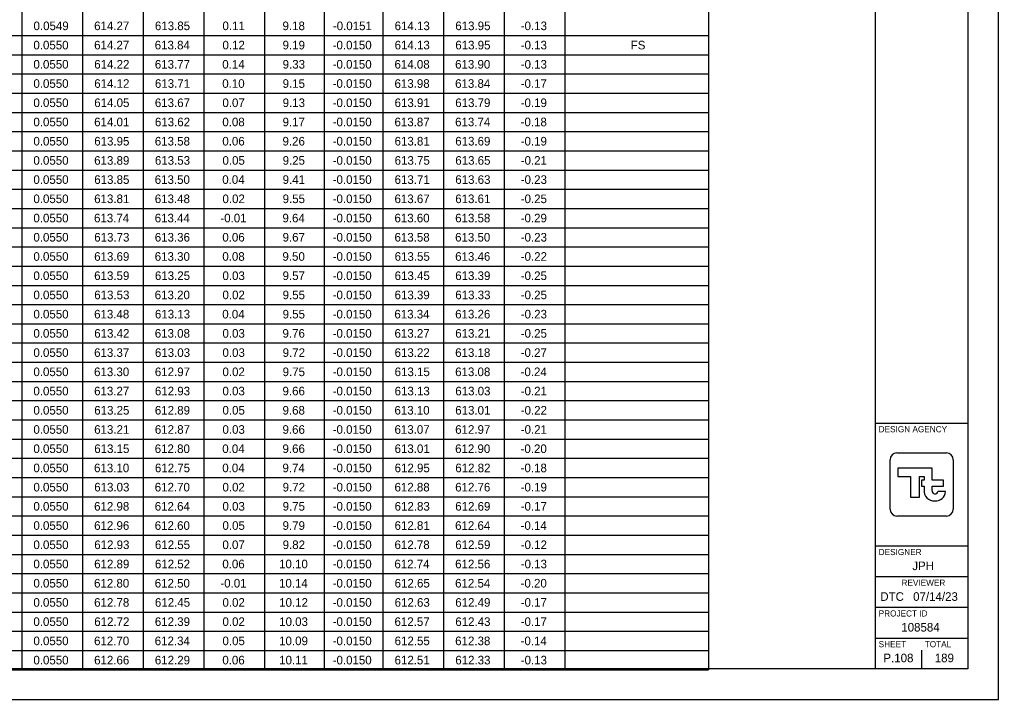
# Model space of a CAD drawing. Extents: x 0 to 34, y 0 to 22.
# Drawn here: x 18.06 to 34, y 0 to 11.07 of the extents above; entities that cross this region are included whole.
import ezdxf

# ---------------------------------------------------------------- set-up
doc = ezdxf.new("R2010")
doc.units = 0
for name, color, linetype in [('SH_Border', 7, 'Continuous'), ('SH_Cut_Line', 7, 'Continuous'), ('SH_Data', 7, 'Continuous'), ('SH_Text', 7, 'Continuous')]:
    doc.layers.add(name, color=color, linetype=linetype)

msp = doc.modelspace()

# ---------------------------------------------------------------- linework, layer by layer
at = {"layer": 'SH_Border'}
for p, q in [((32, 0.5), (32, 21.5)), ((32, 4.5), (33.5, 4.5)), ((32, 2.5), (33.5, 2.5)), ((32, 2), (33.5, 2)), ((32, 1.5), (33.5, 1.5)), ((32, 1), (33.5, 1))]:
    msp.add_line(p, q, dxfattribs=at)
msp.add_lwpolyline([(1.5, 21.5), (33.5, 21.5), (33.5, 0.5), (1.5, 0.5)], close=True, dxfattribs=at)
at = {"layer": 'SH_Cut_Line'}
msp.add_lwpolyline([(0, 0), (34, 0), (34, 22), (0, 22)], close=True, dxfattribs=at)
at = {"layer": 'SH_Data'}
for p, q in [((32.75, 3.5), (32.75, 3.5)), ((32.791, 3.415), (32.791, 3.415)), ((33.136, 3.385), (33.015, 3.385)), ((32.75, 0.5), (32.75, 0.8)), ((32.375, 0.675), (32.375, 0.675))]:
    msp.add_line(p, q, dxfattribs=at)
for points in [[(32.348, 4.014), (33.152, 4.014)], [(32.236, 3.099), (32.236, 3.901)], [(33.264, 3.901), (33.264, 3.099)], [(32.922, 3.399), (32.922, 3.47), (33.107, 3.47), (33.107, 3.568), (32.922, 3.568), (32.922, 3.768), (32.361, 3.768), (32.361, 3.632), (32.566, 3.632), (32.566, 3.294), (32.715, 3.294), (32.715, 3.63), (32.79, 3.63), (32.79, 3.568), (32.748, 3.568), (32.748, 3.47), (32.79, 3.47), (32.79, 3.415), (32.791, 3.415)], [(33.152, 2.986), (32.348, 2.986)]]:
    msp.add_lwpolyline(points, dxfattribs=at)
for centre, radius, start, end in [((32.348, 3.901), 0.113, 90, 180), ((33.152, 3.901), 0.113, 360, 90), ((32.949, 3.392), 0.16, 171.8856, 274.8323), ((32.968, 3.392), 0.0473, 171.8856, 350.9243), ((32.976, 3.392), 0.16, 265.1677, 357.3201), ((32.348, 3.099), 0.113, 180, 270), ((33.152, 3.099), 0.113, 270, 360)]:
    msp.add_arc(centre, radius, start, end, dxfattribs=at)
at = {"layer": 'SH_Text'}
for p, q in [((29.277, 21.5), (29.277, 0.484)), ((26.938, 20.396), (26.938, 0.484)), ((22.046, 19.853), (22.046, 0.484)), ((18.093, 19.54), (18.093, 0.484)), ((19.081, 19.54), (19.081, 0.484)), ((20.07, 19.54), (20.07, 0.484)), ((21.058, 19.54), (21.058, 0.484)), ((23.018, 19.54), (23.018, 0.484)), ((23.973, 19.54), (23.973, 0.484)), ((24.961, 19.54), (24.961, 0.484)), ((25.95, 19.54), (25.95, 0.484)), ((4.225, 10.811), (29.277, 10.811)), ((4.225, 10.498), (29.277, 10.498)), ((4.225, 10.185), (29.277, 10.185)), ((4.225, 9.872), (29.277, 9.872)), ((4.225, 9.559), (29.277, 9.559)), ((4.225, 9.246), (29.277, 9.246)), ((4.225, 8.933), (29.277, 8.933)), ((4.225, 8.62), (29.277, 8.62)), ((4.225, 8.307), (29.277, 8.307)), ((4.225, 7.994), (29.277, 7.994)), ((4.225, 7.681), (29.277, 7.681)), ((4.225, 7.368), (29.277, 7.368)), ((4.225, 7.055), (29.277, 7.055)), ((4.225, 6.742), (29.277, 6.742)), ((4.225, 6.429), (29.277, 6.429)), ((4.225, 6.116), (29.277, 6.116)), ((4.225, 5.804), (29.277, 5.804)), ((4.225, 5.491), (29.277, 5.491)), ((4.225, 5.178), (29.277, 5.178)), ((4.225, 4.865), (29.277, 4.865)), ((4.225, 4.552), (29.277, 4.552)), ((4.225, 4.239), (29.277, 4.239)), ((4.225, 3.926), (29.277, 3.926)), ((4.225, 3.613), (29.277, 3.613)), ((4.225, 3.3), (29.277, 3.3)), ((4.225, 2.987), (29.277, 2.987)), ((4.225, 2.674), (29.277, 2.674)), ((4.225, 2.361), (29.277, 2.361)), ((4.225, 2.048), (29.277, 2.048)), ((4.225, 1.735), (29.277, 1.735)), ((4.225, 1.422), (29.277, 1.422)), ((4.225, 1.109), (29.277, 1.109)), ((4.225, 0.796), (29.277, 0.796)), ((4.225, 0.484), (29.277, 0.484))]:
    msp.add_line(p, q, dxfattribs=at)

# ---------------------------------------------------------------- texts
at = {"layer": 'SH_Data'}
for s, height, p in [('DESIGN AGENCY', 0.1, (32.05, 4.35)), ('DESIGNER', 0.1, (32.05, 2.35)), ('JPH', 0.14, (32.598, 2.105)), ('REVIEWER', 0.1, (32.422, 1.85)), ('DTC', 0.14, (32.076, 1.605)), ('07/14/23', 0.14, (32.611, 1.605)), ('PROJECT ID', 0.1, (32.05, 1.35)), ('108584', 0.14, (32.418, 1.105)), ('SHEET', 0.1, (32.05, 0.85)), ('TOTAL', 0.1, (32.8, 0.85)), ('P.108', 0.14, (32.127, 0.605)), ('189', 0.14, (32.963, 0.605))]:
    msp.add_text(s, height=height, dxfattribs=at).set_placement(p)
at = {"layer": 'SH_Text'}
for s, p in [('0.0549', (18.286, 10.897)), ('614.27', (19.273, 10.897)), ('613.85', (20.263, 10.897)), ('0.11', (21.363, 10.897)), ('9.18', (22.341, 10.897)), ('-0.0151', (23.161, 10.897)), ('614.13', (24.167, 10.897)), ('613.95', (25.155, 10.897)), ('-0.13', (26.221, 10.897)), ('0.0550', (18.284, 10.584)), ('614.27', (19.273, 10.584)), ('613.84', (20.26, 10.584)), ('0.12', (21.363, 10.584)), ('9.19', (22.342, 10.584)), ('-0.0150', (23.158, 10.584)), ('614.13', (24.167, 10.584)), ('613.95', (25.155, 10.584)), ('-0.13', (26.221, 10.584)), ('FS', (28.012, 10.584)), ('0.0550', (18.284, 10.271)), ('614.22', (19.275, 10.271)), ('613.77', (20.262, 10.271)), ('0.14', (21.36, 10.271)), ('9.33', (22.343, 10.271)), ('-0.0150', (23.158, 10.271)), ('614.08', (24.165, 10.271)), ('613.90', (25.152, 10.271)), ('-0.13', (26.221, 10.271)), ('0.0550', (18.284, 9.958)), ('614.12', (19.275, 9.958)), ('613.71', (20.263, 9.958)), ('0.10', (21.36, 9.958)), ('9.15', (22.343, 9.958)), ('-0.0150', (23.158, 9.958)), ('613.98', (24.165, 9.958)), ('613.84', (25.152, 9.958)), ('-0.17', (26.22, 9.958)), ('0.0550', (18.284, 9.645)), ('614.05', (19.275, 9.645)), ('613.67', (20.262, 9.645)), ('0.07', (21.362, 9.645)), ('9.13', (22.343, 9.645)), ('-0.0150', (23.158, 9.645)), ('613.91', (24.166, 9.645)), ('613.79', (25.154, 9.645)), ('-0.19', (26.22, 9.645)), ('0.0550', (18.284, 9.332)), ('614.01', (19.274, 9.332)), ('613.62', (20.263, 9.332)), ('0.08', (21.361, 9.332)), ('9.17', (22.342, 9.332)), ('-0.0150', (23.158, 9.332)), ('613.87', (24.165, 9.332)), ('613.74', (25.152, 9.332)), ('-0.18', (26.219, 9.332)), ('0.0550', (18.284, 9.019)), ('613.95', (19.275, 9.019)), ('613.58', (20.261, 9.019)), ('0.06', (21.361, 9.019)), ('9.26', (22.341, 9.019)), ('-0.0150', (23.158, 9.019)), ('613.81', (24.166, 9.019)), ('613.69', (25.154, 9.019)), ('-0.19', (26.22, 9.019)), ('0.0550', (18.284, 8.706)), ('613.89', (19.274, 8.706)), ('613.53', (20.263, 8.706)), ('0.05', (21.363, 8.706)), ('9.25', (22.343, 8.706)), ('-0.0150', (23.158, 8.706)), ('613.75', (24.167, 8.706)), ('613.65', (25.155, 8.706)), ('-0.21', (26.221, 8.706)), ('0.0550', (18.284, 8.394)), ('613.85', (19.275, 8.394)), ('613.50', (20.26, 8.394)), ('0.04', (21.36, 8.394)), ('9.41', (22.343, 8.394)), ('-0.0150', (23.158, 8.394)), ('613.71', (24.166, 8.394)), ('613.63', (25.155, 8.394)), ('-0.23', (26.221, 8.394)), ('0.0550', (18.284, 8.081)), ('613.81', (19.274, 8.081)), ('613.48', (20.261, 8.081)), ('0.02', (21.363, 8.081)), ('9.55', (22.343, 8.081)), ('-0.0150', (23.158, 8.081)), ('613.67', (24.165, 8.081)), ('613.61', (25.154, 8.081)), ('-0.25', (26.221, 8.081)), ('0.0550', (18.284, 7.768)), ('613.74', (19.272, 7.768)), ('613.44', (20.26, 7.768)), ('-0.01', (21.329, 7.768)), ('9.64', (22.34, 7.768)), ('-0.0150', (23.158, 7.768)), ('613.60', (24.164, 7.768)), ('613.58', (25.153, 7.768)), ('-0.29', (26.22, 7.768)), ('0.0550', (18.284, 7.455)), ('613.73', (19.275, 7.455)), ('613.36', (20.261, 7.455)), ('0.06', (21.361, 7.455)), ('9.67', (22.342, 7.455)), ('-0.0150', (23.158, 7.455)), ('613.58', (24.165, 7.455)), ('613.50', (25.152, 7.455)), ('-0.23', (26.221, 7.455)), ('0.0550', (18.284, 7.142)), ('613.69', (19.274, 7.142)), ('613.30', (20.26, 7.142)), ('0.08', (21.361, 7.142)), ('9.50', (22.34, 7.142)), ('-0.0150', (23.158, 7.142)), ('613.55', (24.167, 7.142)), ('613.46', (25.153, 7.142)), ('-0.22', (26.221, 7.142)), ('0.0550', (18.284, 6.829)), ('613.59', (19.274, 6.829)), ('613.25', (20.263, 6.829)), ('0.03', (21.363, 6.829)), ('9.57', (22.342, 6.829)), ('-0.0150', (23.158, 6.829)), ('613.45', (24.167, 6.829)), ('613.39', (25.154, 6.829)), ('-0.25', (26.221, 6.829)), ('0.0550', (18.284, 6.516)), ('613.53', (19.275, 6.516)), ('613.20', (20.26, 6.516)), ('0.02', (21.363, 6.516)), ('9.55', (22.343, 6.516)), ('-0.0150', (23.158, 6.516)), ('613.39', (24.166, 6.516)), ('613.33', (25.155, 6.516)), ('-0.25', (26.221, 6.516)), ('0.0550', (18.284, 6.203)), ('613.48', (19.273, 6.203)), ('613.13', (20.263, 6.203)), ('0.04', (21.36, 6.203)), ('9.55', (22.343, 6.203)), ('-0.0150', (23.158, 6.203)), ('613.34', (24.163, 6.203)), ('613.26', (25.153, 6.203)), ('-0.23', (26.221, 6.203)), ('0.0550', (18.284, 5.89)), ('613.42', (19.275, 5.89)), ('613.08', (20.261, 5.89)), ('0.03', (21.363, 5.89)), ('9.76', (22.341, 5.89)), ('-0.0150', (23.158, 5.89)), ('613.27', (24.165, 5.89)), ('613.21', (25.154, 5.89)), ('-0.25', (26.221, 5.89)), ('0.0550', (18.284, 5.577)), ('613.37', (19.273, 5.577)), ('613.03', (20.263, 5.577)), ('0.03', (21.363, 5.577)), ('9.72', (22.343, 5.577)), ('-0.0150', (23.158, 5.577)), ('613.22', (24.166, 5.577)), ('613.18', (25.153, 5.577)), ('-0.27', (26.22, 5.577)), ('0.0550', (18.284, 5.264)), ('613.30', (19.272, 5.264)), ('612.97', (20.262, 5.264)), ('0.02', (21.363, 5.264)), ('9.75', (22.343, 5.264)), ('-0.0150', (23.158, 5.264)), ('613.15', (24.167, 5.264)), ('613.08', (25.153, 5.264)), ('-0.24', (26.218, 5.264)), ('0.0550', (18.284, 4.951)), ('613.27', (19.273, 4.951)), ('612.93', (20.263, 4.951)), ('0.03', (21.363, 4.951)), ('9.66', (22.341, 4.951)), ('-0.0150', (23.158, 4.951)), ('613.13', (24.167, 4.951)), ('613.03', (25.155, 4.951)), ('-0.21', (26.221, 4.951)), ('0.0550', (18.284, 4.638)), ('613.25', (19.275, 4.638)), ('612.89', (20.262, 4.638)), ('0.05', (21.363, 4.638)), ('9.68', (22.341, 4.638)), ('-0.0150', (23.158, 4.638)), ('613.10', (24.164, 4.638)), ('613.01', (25.154, 4.638)), ('-0.22', (26.221, 4.638)), ('0.0550', (18.284, 4.325)), ('613.21', (19.274, 4.325)), ('612.87', (20.262, 4.325)), ('0.03', (21.363, 4.325)), ('9.66', (22.341, 4.325)), ('-0.0150', (23.158, 4.325)), ('613.07', (24.165, 4.325)), ('612.97', (25.153, 4.325)), ('-0.21', (26.221, 4.325)), ('0.0550', (18.284, 4.012)), ('613.15', (19.275, 4.012)), ('612.80', (20.26, 4.012)), ('0.04', (21.36, 4.012)), ('9.66', (22.341, 4.012)), ('-0.0150', (23.158, 4.012)), ('613.01', (24.166, 4.012)), ('612.90', (25.152, 4.012)), ('-0.20', (26.218, 4.012)), ('0.0550', (18.284, 3.699)), ('613.10', (19.272, 3.699)), ('612.75', (20.263, 3.699)), ('0.04', (21.36, 3.699)), ('9.74', (22.34, 3.699)), ('-0.0150', (23.158, 3.699)), ('612.95', (24.167, 3.699)), ('612.82', (25.155, 3.699)), ('-0.18', (26.219, 3.699)), ('0.0550', (18.284, 3.386)), ('613.03', (19.275, 3.386)), ('612.70', (20.26, 3.386)), ('0.02', (21.363, 3.386)), ('9.72', (22.343, 3.386)), ('-0.0150', (23.158, 3.386)), ('612.88', (24.165, 3.386)), ('612.76', (25.153, 3.386)), ('-0.19', (26.22, 3.386)), ('0.0550', (18.284, 3.074)), ('612.98', (19.273, 3.074)), ('612.64', (20.26, 3.074)), ('0.03', (21.363, 3.074)), ('9.75', (22.343, 3.074)), ('-0.0150', (23.158, 3.074)), ('612.83', (24.167, 3.074)), ('612.69', (25.154, 3.074)), ('-0.17', (26.22, 3.074)), ('0.0550', (18.284, 2.761)), ('612.96', (19.273, 2.761)), ('612.60', (20.26, 2.761)), ('0.05', (21.363, 2.761)), ('9.79', (22.342, 2.761)), ('-0.0150', (23.158, 2.761)), ('612.81', (24.166, 2.761)), ('612.64', (25.152, 2.761)), ('-0.14', (26.218, 2.761)), ('0.0550', (18.284, 2.448)), ('612.93', (19.275, 2.448)), ('612.55', (20.263, 2.448)), ('0.07', (21.362, 2.448)), ('9.82', (22.343, 2.448)), ('-0.0150', (23.158, 2.448)), ('612.78', (24.165, 2.448)), ('612.59', (25.154, 2.448)), ('-0.12', (26.221, 2.448)), ('0.0550', (18.284, 2.135)), ('612.89', (19.274, 2.135)), ('612.52', (20.263, 2.135)), ('0.06', (21.361, 2.135)), ('10.10', (22.285, 2.135)), ('-0.0150', (23.158, 2.135)), ('612.74', (24.163, 2.135)), ('612.56', (25.153, 2.135)), ('-0.13', (26.221, 2.135)), ('0.0550', (18.284, 1.822)), ('612.80', (19.272, 1.822)), ('612.50', (20.26, 1.822)), ('-0.01', (21.329, 1.822)), ('10.14', (22.284, 1.822)), ('-0.0150', (23.158, 1.822)), ('612.65', (24.167, 1.822)), ('612.54', (25.152, 1.822)), ('-0.20', (26.218, 1.822)), ('0.0550', (18.284, 1.509)), ('612.78', (19.273, 1.509)), ('612.45', (20.263, 1.509)), ('0.02', (21.363, 1.509)), ('10.12', (22.287, 1.509)), ('-0.0150', (23.158, 1.509)), ('612.63', (24.167, 1.509)), ('612.49', (25.154, 1.509)), ('-0.17', (26.22, 1.509)), ('0.0550', (18.284, 1.196)), ('612.72', (19.275, 1.196)), ('612.39', (20.262, 1.196)), ('0.02', (21.363, 1.196)), ('10.03', (22.287, 1.196)), ('-0.0150', (23.158, 1.196)), ('612.57', (24.165, 1.196)), ('612.43', (25.155, 1.196)), ('-0.17', (26.22, 1.196)), ('0.0550', (18.284, 0.883)), ('612.70', (19.272, 0.883)), ('612.34', (20.26, 0.883)), ('0.05', (21.363, 0.883)), ('10.09', (22.286, 0.883)), ('-0.0150', (23.158, 0.883)), ('612.55', (24.167, 0.883)), ('612.38', (25.153, 0.883)), ('-0.14', (26.218, 0.883)), ('0.0550', (18.284, 0.57)), ('612.66', (19.273, 0.57)), ('612.29', (20.262, 0.57)), ('0.06', (21.361, 0.57)), ('10.11', (22.287, 0.57)), ('-0.0150', (23.158, 0.57)), ('612.51', (24.166, 0.57)), ('612.33', (25.155, 0.57)), ('-0.13', (26.221, 0.57))]:
    msp.add_text(s, height=0.14, dxfattribs=at).set_placement(p)

doc.saveas('drawing.dxf')
